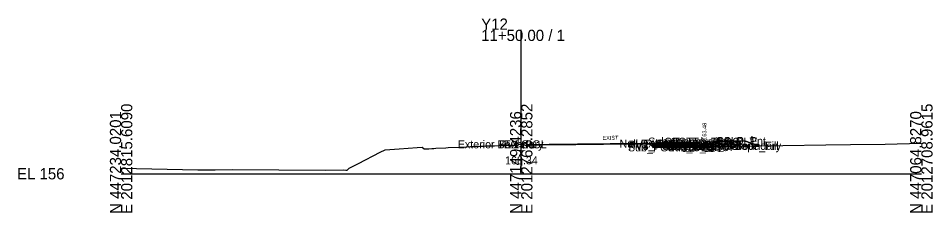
# Model space of a CAD drawing. Extents: x -26 to 1203, y -10 to 9542.
# Drawn here: x -25.7 to 202.8, y 2990.3 to 3038.7 of the extents above; entities that cross this region are included whole.
import ezdxf

# ---------------------------------------------------------------- set-up
doc = ezdxf.new("R2010")
doc.units = 0
for name, color, linetype in [('Default', 7, 'Continuous'), ('Exist Cross Section Cell', 7, 'Continuous'), ('Exist XS Center Line Elevation Label', 7, 'Continuous'), ('Exist XS Ground Line', 7, 'Continuous'), ('Prop CMT Conc Surface', 7, 'Continuous'), ('Prop CMT Concrete Structures', 7, 'Continuous'), ('Prop CMT Pvmt Course 1', 7, 'Continuous'), ('Prop CMT Pvmt Course 1 CG', 7, 'Continuous'), ('Prop CMT Pvmt Course 2', 7, 'Continuous'), ('Prop CMT Pvmt Course 3', 7, 'Continuous'), ('Prop CMT Pvmt Surface', 7, 'Continuous'), ('Prop CMT Slope Grass', 7, 'Continuous'), ('Prop CMT Subgrade Earthwork', 7, 'Continuous'), ('Prop XS Earthwork Shape', 7, 'Continuous'), ('Prop XS Hydro Elevations', 7, 'Continuous'), ('Prop XS SE Text', 7, 'Continuous'), ('Prop XS Side Slope Text', 7, 'Continuous'), ('Scratch_Level_0', 7, 'Continuous')]:
    doc.layers.add(name, color=color, linetype=linetype)

msp = doc.modelspace()

# ---------------------------------------------------------------- linework, layer by layer
at = {"layer": 'Exist Cross Section Cell'}
for p, q in [((100, 3000), (100, 3035.89)), ((0, 3000), (100, 3000)), ((100, 3000), (200, 3000))]:
    msp.add_line(p, q, dxfattribs=at)
at = {"layer": 'Exist XS Ground Line'}
msp.add_lwpolyline([(0, 3001.37), (19.2, 3001.01), (23.55, 3001.02), (27.79, 3001.04), (51.06, 3000.92), (55.49, 3001), (56.18, 3000.93), (56.49, 3000.91), (56.99, 3001.41), (59.31, 3002.58), (64.77, 3005.41), (66.01, 3005.93), (69.48, 3006.23), (73.98, 3006.57), (75.21, 3006.67), (75.72, 3006.22), (76.91, 3006.25), (77.68, 3006.28), (78.15, 3006.31), (78.69, 3006.34), (81.2, 3006.48), (81.76, 3006.51), (84.49, 3006.65), (86.43, 3006.75), (87.31, 3006.79), (88.12, 3006.83), (89.67, 3006.88), (90.65, 3006.91), (91.11, 3006.92), (92.47, 3006.96), (93.32, 3006.98), (94.28, 3007.01), (96.27, 3007.08), (97.84, 3007.13), (98.4, 3007.12), (98.97, 3007.04), (99.57, 3007.34), (100, 3007.34), (100.45, 3007.34), (101.05, 3007.04), (101.73, 3007.18), (102.26, 3007.19), (105.21, 3007.23), (107, 3007.27), (108.14, 3007.29), (108.82, 3007.3), (109.9, 3007.3), (111.02, 3007.31), (111.9, 3007.31), (113.63, 3007.33), (114.03, 3007.34), (114.58, 3007.35), (116.97, 3007.38), (119.24, 3007.4), (119.92, 3007.41), (120.58, 3007.41), (122.42, 3007.42), (123.02, 3007.42), (123.92, 3007.43), (125.09, 3007.44), (125.83, 3007.45), (126.91, 3007.45), (129.07, 3007.47), (131.68, 3007.49), (132.25, 3007.5), (132.87, 3007.5), (134.76, 3007.57), (135.4, 3007.92), (136.06, 3007.91), (138.67, 3007.89), (139.72, 3007.88), (141.88, 3007.88), (144.88, 3007.49), (149.96, 3006.76), (153.18, 3006.88), (159.07, 3006.96), (165.39, 3007.08), (176.09, 3007.19), (182.33, 3007.29), (190.93, 3007.4), (200, 3007.6)], dxfattribs=at)
at = {"layer": 'Prop CMT Conc Surface'}
msp.add_lwpolyline([(143.79, 3007.55), (145.79, 3007.48), (145.79, 3007.98), (146.29, 3007.98)], dxfattribs=at)
at = {"layer": 'Prop CMT Concrete Structures'}
for points in [[(143.79, 3007.55), (145.79, 3007.48), (145.79, 3007.98), (146.29, 3007.98)], [(146.29, 3007.98), (146.29, 3006.98), (143.79, 3006.97)], [(143.79, 3006.97), (143.79, 3007.55)]]:
    msp.add_lwpolyline(points, dxfattribs=at)
at = {"layer": 'Prop CMT Pvmt Course 1'}
for points in [[(132.87, 3007.5), (132.25, 3007.5), (132.17, 3007.5), (131.68, 3007.49), (129.07, 3007.47), (128.79, 3007.46), (128.62, 3007.46), (126.91, 3007.45), (125.83, 3007.45), (125.09, 3007.44), (123.92, 3007.43), (123.02, 3007.42), (122.42, 3007.42), (122.24, 3007.42), (120.58, 3007.41), (119.92, 3007.41), (119.24, 3007.4), (116.97, 3007.38), (114.58, 3007.35), (114.03, 3007.34), (113.63, 3007.33), (111.97, 3007.31), (111.9, 3007.31), (111.02, 3007.31), (109.9, 3007.3), (108.82, 3007.3), (108.14, 3007.29), (107, 3007.27), (105.21, 3007.23), (105.18, 3007.23), (105.13, 3007.23), (102.26, 3007.19), (101.73, 3007.18), (101.47, 3007.18), (101.39, 3007.15), (101.05, 3007.04), (100.54, 3007.3), (100.45, 3007.34), (100, 3007.34)], [(132.87, 3007.5), (143.79, 3007.55)], [(132.87, 3007.5), (132.87, 3007.5)], [(132.87, 3007.25), (132.87, 3007.5)], [(143.79, 3007.55), (143.79, 3007.3)], [(100, 3007.34), (100, 3007.34)], [(143.79, 3007.3), (132.87, 3007.25)]]:
    msp.add_lwpolyline(points, dxfattribs=at)
at = {"layer": 'Prop CMT Pvmt Course 1 CG'}
for points in [[(143.79, 3006.97), (146.79, 3006.98), (147.12, 3006.65)], [(143.79, 3006.63), (143.79, 3006.97)], [(147.12, 3006.65), (143.79, 3006.63)]]:
    msp.add_lwpolyline(points, dxfattribs=at)
at = {"layer": 'Prop CMT Pvmt Course 2'}
for points in [[(132.87, 3007.25), (143.79, 3007.3)], [(132.87, 3006.92), (132.87, 3007.25)], [(143.79, 3006.97), (132.87, 3006.92)], [(143.79, 3007.3), (143.79, 3006.97)]]:
    msp.add_lwpolyline(points, dxfattribs=at)
at = {"layer": 'Prop CMT Pvmt Course 3'}
for points in [[(132.87, 3006.92), (143.79, 3006.97)], [(132.87, 3006.58), (132.87, 3006.92)], [(143.79, 3006.63), (132.87, 3006.58)], [(143.79, 3006.97), (143.79, 3006.63)]]:
    msp.add_lwpolyline(points, dxfattribs=at)
at = {"layer": 'Prop CMT Pvmt Surface'}
msp.add_lwpolyline([(132.87, 3007.5), (143.79, 3007.55)], dxfattribs=at)
at = {"layer": 'Prop CMT Slope Grass'}
msp.add_lwpolyline([(146.29, 3007.98), (155.79, 3008.17), (159.41, 3006.96)], dxfattribs=at)
at = {"layer": 'Prop CMT Subgrade Earthwork'}
for points in [[(132.87, 3006.58), (132.87, 3007.5)], [(143.79, 3006.63), (147.12, 3006.65), (148.5, 3008.02)], [(132.87, 3006.58), (143.79, 3006.63)], [(143.79, 3006.63), (132.87, 3006.58)]]:
    msp.add_lwpolyline(points, dxfattribs=at)
at = {"layer": 'Prop XS Earthwork Shape'}
for points in [[(136.06, 3007.91), (138.67, 3007.89), (139.72, 3007.88), (141.88, 3007.88), (144.63, 3007.52), (143.79, 3007.55), (132.87, 3007.5), (134.76, 3007.57), (135.4, 3007.92)], [(146.29, 3007.29), (146.29, 3006.98), (143.79, 3006.97), (143.79, 3007.55), (132.87, 3007.5), (132.87, 3006.58), (143.79, 3006.63), (147.12, 3006.65), (147.57, 3007.1)], [(144.88, 3007.49), (146.29, 3007.29), (146.29, 3006.98), (143.79, 3006.97), (143.79, 3007.55), (144.63, 3007.52)], [(149.96, 3006.76), (153.18, 3006.88), (159.07, 3006.96), (159.41, 3006.96), (155.79, 3008.17), (148.5, 3008.02), (147.57, 3007.1)]]:
    msp.add_lwpolyline(points, close=True, dxfattribs=at)

# ---------------------------------------------------------------- texts
at = {"layer": 'Default'}
msp.add_text('-', height=0.0001, dxfattribs=at).set_placement((0, 3000))
at = {"layer": 'Exist Cross Section Cell'}
for s, p in [('Y12', (90, 3035.89)), ('11+50.00 / 1', (90, 3033.09)), ('EL 156', (-26, 2998.6))]:
    msp.add_text(s, height=2.8, dxfattribs=at).set_placement(p)
for s, p in [('E 2012815.6090', (2.8, 2990)), ('E 2012762.2852', (102.8, 2990)), ('E 2012708.9615', (202.8, 2990)), ('N 447234.0201', (0, 2990)), ('N 447149.4236', (100, 2990)), ('N 447064.8270', (200, 2990))]:
    msp.add_text(s, height=2.8, rotation=90, dxfattribs=at).set_placement(p)
at = {"layer": 'Exist XS Center Line Elevation Label'}
msp.add_text('163.34', height=2, dxfattribs=at).set_placement((95.96, 3002.34))
at = {"layer": 'Prop XS Hydro Elevations'}
msp.add_text('163.48', height=1, rotation=90, dxfattribs=at).set_placement((146.29, 3008.48))
at = {"layer": 'Prop XS SE Text'}
msp.add_text('EXIST', height=1, rotation=0.2702, dxfattribs=at).set_placement((120.31, 3008.44))
at = {"layer": 'Prop XS Side Slope Text'}
msp.add_text('3:1', height=1, rotation=341.5651, dxfattribs=at).set_placement((157.08, 3008.53))
at = {"layer": 'Scratch_Level_0'}
for s, p in [('Exterior Boundary', (84.14, 3006.34)), ('PV1_PGL', (94.47, 3006.34)), ('EX CL', (95.67, 3006.34)), ('Null Ex EOP', (124.57, 3006.5)), ('Sub_PGL', (126.68, 3005.58)), ('PV2_PGL', (126.78, 3006.25)), ('PV3_PGL', (126.78, 3005.92)), ('PV1', (130.95, 3006.5)), ('Sub_Trench_Out_DLT', (131.76, 3007.02)), ('CG_Top_Face', (135.74, 3006.98)), ('CG1_Shelf_Out', (136.03, 3005.98)), ('CG_Bot_IE', (136.4, 3005.97)), ('Sub_OEOT', (136.56, 3005.63)), ('CG_Top_Gut', (136.72, 3006.48)), ('PV2_OEOT', (136.66, 3006.3)), ('PV3_OEOT', (136.66, 3005.97)), ('CG_Top_BOC', (137.27, 3006.98)), ('CG_Bot_BOC', (137.3, 3005.98)), ('PV1_OEOT', (137.22, 3006.55)), ('Sub_OEOP', (139.92, 3005.65)), ('Exterior Boundary', (143.55, 3005.96)), ('CSLP_Pnt', (148.66, 3007.17)), ('Slope_Fill', (152.62, 3005.96))]:
    msp.add_text(s, height=2, dxfattribs=at).set_placement(p)

doc.saveas('drawing.dxf')
